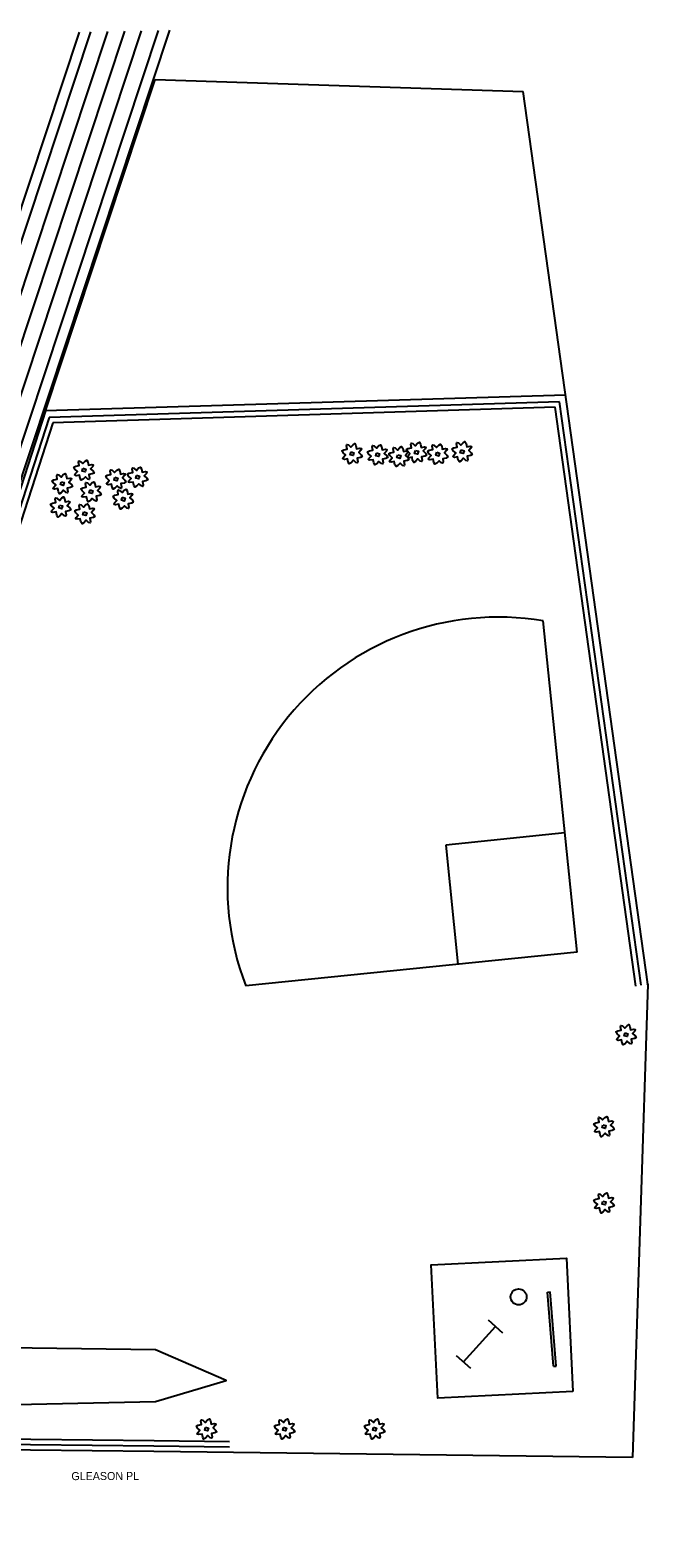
# Model space of a CAD drawing. Extents: x 1810019 to 1811399, y 1074962 to 1076105.
# Drawn here: x 1810935 to 1811399, y 1074973 to 1076105 of the extents above; entities that cross this region are included whole.
import ezdxf

# ---------------------------------------------------------------- set-up
doc = ezdxf.new("R2010")
doc.units = 0
for name, color, linetype in [('Environmental-New trees', 7, 'Continuous'), ('Roadway-Centerline main', 7, 'Continuous'), ('Roadway-Edge of pavement', 7, 'Continuous'), ('Roadway-Edge of shoulder', 7, 'Continuous'), ('Roadway-Land lines', 7, 'Continuous'), ('Roadway-Sidewalks', 7, 'Continuous'), ('Scratch-1', 7, 'Continuous'), ('Text-Route label', 7, 'Continuous')]:
    doc.layers.add(name, color=color, linetype=linetype)

msp = doc.modelspace()

# ---------------------------------------------------------------- linework, layer by layer
at = {"layer": 'Environmental-New trees'}
for points in [[(1811170.3, 1075783.1), (1811170.6, 1075784.2), (1811172.3, 1075786.1), (1811170.4, 1075787.7), (1811169.6, 1075789.1), (1811171, 1075789.9), (1811173.5, 1075790.4), (1811173, 1075792.9), (1811173.3, 1075793.9), (1811174.4, 1075793.6), (1811176.3, 1075791.9), (1811178, 1075793.8), (1811179.3, 1075794.6), (1811180.1, 1075793.2), (1811180.6, 1075790.7), (1811183.1, 1075791.2), (1811184.2, 1075790.9), (1811183.8, 1075789.7), (1811182.2, 1075787.9), (1811184, 1075786.3), (1811184.8, 1075784.9), (1811183.4, 1075784.1), (1811180.9, 1075783.6), (1811181.4, 1075781.1), (1811181.1, 1075780.1), (1811180, 1075780.4), (1811178.2, 1075782.1), (1811176.5, 1075780.2), (1811175.1, 1075779.4), (1811174.3, 1075780.8), (1811173.8, 1075783.3), (1811171.4, 1075782.8)], [(1811189.5, 1075782.4), (1811189.8, 1075783.4), (1811191.5, 1075785.3), (1811189.6, 1075787), (1811188.8, 1075788.4), (1811190.2, 1075789.1), (1811192.7, 1075789.6), (1811192.2, 1075792.1), (1811192.5, 1075793.2), (1811193.6, 1075792.9), (1811195.5, 1075791.2), (1811197.2, 1075793.1), (1811198.5, 1075793.8), (1811199.3, 1075792.4), (1811199.8, 1075790), (1811202.3, 1075790.4), (1811203.3, 1075790.1), (1811203, 1075789), (1811201.3, 1075787.2), (1811203.2, 1075785.5), (1811204, 1075784.1), (1811202.6, 1075783.4), (1811200.1, 1075782.9), (1811200.6, 1075780.4), (1811200.3, 1075779.3), (1811199.2, 1075779.6), (1811197.3, 1075781.3), (1811195.7, 1075779.4), (1811194.3, 1075778.7), (1811193.5, 1075780.1), (1811193, 1075782.5), (1811190.5, 1075782.1)], [(1811205.4, 1075781), (1811205.7, 1075782.1), (1811207.4, 1075783.9), (1811205.5, 1075785.6), (1811204.7, 1075787), (1811206.1, 1075787.8), (1811208.6, 1075788.3), (1811208.1, 1075790.7), (1811208.4, 1075791.8), (1811209.5, 1075791.5), (1811211.4, 1075789.8), (1811213.1, 1075791.7), (1811214.4, 1075792.5), (1811215.2, 1075791.1), (1811215.7, 1075788.6), (1811218.2, 1075789.1), (1811219.3, 1075788.8), (1811218.9, 1075787.6), (1811217.3, 1075785.8), (1811219.1, 1075784.1), (1811219.9, 1075782.7), (1811218.5, 1075782), (1811216, 1075781.5), (1811216.5, 1075779), (1811216.2, 1075777.9), (1811215.1, 1075778.2), (1811213.3, 1075779.9), (1811211.6, 1075778.1), (1811210.2, 1075777.3), (1811209.4, 1075778.7), (1811208.9, 1075781.2), (1811206.5, 1075780.7)], [(1811218.7, 1075784.2), (1811219, 1075785.3), (1811220.7, 1075787.2), (1811218.8, 1075788.9), (1811218.1, 1075790.2), (1811219.4, 1075791), (1811221.9, 1075791.5), (1811221.4, 1075794), (1811221.7, 1075795), (1811222.8, 1075794.7), (1811224.7, 1075793), (1811226.4, 1075794.9), (1811227.8, 1075795.7), (1811228.6, 1075794.3), (1811229, 1075791.8), (1811231.5, 1075792.3), (1811232.6, 1075792), (1811232.2, 1075790.8), (1811230.6, 1075789.1), (1811232.4, 1075787.4), (1811233.2, 1075786), (1811231.9, 1075785.2), (1811229.4, 1075784.7), (1811229.8, 1075782.2), (1811229.5, 1075781.2), (1811228.4, 1075781.5), (1811226.6, 1075783.2), (1811224.9, 1075781.3), (1811223.5, 1075780.5), (1811222.7, 1075781.9), (1811222.3, 1075784.4), (1811219.8, 1075783.9)], [(1811224.9, 1075789.5), (1811227, 1075788.9), (1811226.4, 1075786.7), (1811224.2, 1075787.3)], [(1811234.6, 1075782.8), (1811234.9, 1075783.9), (1811236.6, 1075785.8), (1811234.7, 1075787.5), (1811234, 1075788.9), (1811235.3, 1075789.6), (1811237.8, 1075790.1), (1811237.4, 1075792.6), (1811237.7, 1075793.7), (1811238.7, 1075793.4), (1811240.6, 1075791.7), (1811242.3, 1075793.5), (1811243.7, 1075794.3), (1811244.5, 1075792.9), (1811244.9, 1075790.5), (1811247.4, 1075790.9), (1811248.5, 1075790.6), (1811248.1, 1075789.5), (1811246.5, 1075787.7), (1811248.4, 1075786), (1811249.1, 1075784.6), (1811247.8, 1075783.8), (1811245.3, 1075783.3), (1811245.7, 1075780.9), (1811245.4, 1075779.8), (1811244.4, 1075780.1), (1811242.5, 1075781.8), (1811240.8, 1075779.9), (1811239.4, 1075779.1), (1811238.6, 1075780.5), (1811238.2, 1075783), (1811235.7, 1075782.5)], [(1811253, 1075784.7), (1811253.3, 1075785.7), (1811255, 1075787.6), (1811253.1, 1075789.3), (1811252.3, 1075790.7), (1811253.7, 1075791.4), (1811256.2, 1075791.9), (1811255.7, 1075794.4), (1811256, 1075795.5), (1811257.1, 1075795.2), (1811259, 1075793.5), (1811260.7, 1075795.3), (1811262, 1075796.1), (1811262.8, 1075794.7), (1811263.3, 1075792.3), (1811265.8, 1075792.7), (1811266.8, 1075792.4), (1811266.5, 1075791.3), (1811264.8, 1075789.5), (1811266.7, 1075787.8), (1811267.5, 1075786.4), (1811266.1, 1075785.6), (1811263.6, 1075785.2), (1811264.1, 1075782.7), (1811263.8, 1075781.6), (1811262.7, 1075781.9), (1811260.9, 1075783.6), (1811259.2, 1075781.7), (1811257.8, 1075781), (1811257, 1075782.3), (1811256.5, 1075784.8), (1811254, 1075784.3)], [(1811259.1, 1075789.9), (1811261.3, 1075789.3), (1811260.7, 1075787.2), (1811258.5, 1075787.8)], [(1810969, 1075770.8), (1810969.3, 1075771.9), (1810971, 1075773.7), (1810969.1, 1075775.4), (1810968.3, 1075776.8), (1810969.7, 1075777.6), (1810972.2, 1075778.1), (1810971.7, 1075780.5), (1810972, 1075781.6), (1810973.1, 1075781.3), (1810975, 1075779.6), (1810976.7, 1075781.5), (1810978, 1075782.3), (1810978.8, 1075780.9), (1810979.3, 1075778.4), (1810981.8, 1075778.9), (1810982.8, 1075778.6), (1810982.5, 1075777.4), (1810980.8, 1075775.6), (1810982.7, 1075773.9), (1810983.5, 1075772.5), (1810982.1, 1075771.8), (1810979.6, 1075771.3), (1810980.1, 1075768.8), (1810979.8, 1075767.7), (1810978.7, 1075768), (1810976.9, 1075769.7), (1810975.2, 1075767.9), (1810973.8, 1075767.1), (1810973, 1075768.5), (1810972.5, 1075770.9), (1810970, 1075770.5)], [(1811176.4, 1075788.4), (1811178.6, 1075787.8), (1811178, 1075785.6), (1811175.8, 1075786.2)], [(1811195.6, 1075787.6), (1811197.8, 1075787), (1811197.2, 1075784.9), (1811195, 1075785.5)], [(1811211.5, 1075786.3), (1811213.7, 1075785.7), (1811213.1, 1075783.5), (1811210.9, 1075784.1)], [(1811240.8, 1075788.1), (1811242.9, 1075787.5), (1811242.3, 1075785.3), (1811240.2, 1075786)], [(1810952.6, 1075760.7), (1810952.9, 1075761.7), (1810954.6, 1075763.6), (1810952.7, 1075765.3), (1810952, 1075766.7), (1810953.3, 1075767.4), (1810955.8, 1075767.9), (1810955.4, 1075770.4), (1810955.7, 1075771.5), (1810956.7, 1075771.2), (1810958.6, 1075769.5), (1810960.3, 1075771.3), (1810961.7, 1075772.1), (1810962.5, 1075770.7), (1810962.9, 1075768.3), (1810965.4, 1075768.7), (1810966.5, 1075768.4), (1810966.1, 1075767.3), (1810964.5, 1075765.5), (1810966.4, 1075763.8), (1810967.1, 1075762.4), (1810965.8, 1075761.7), (1810963.3, 1075761.2), (1810963.7, 1075758.7), (1810963.4, 1075757.6), (1810962.4, 1075757.9), (1810960.5, 1075759.6), (1810958.8, 1075757.7), (1810957.4, 1075757), (1810956.6, 1075758.4), (1810956.2, 1075760.8), (1810953.7, 1075760.3)], [(1810975.1, 1075776.1), (1810977.3, 1075775.4), (1810976.7, 1075773.3), (1810974.5, 1075773.9)], [(1810992.8, 1075764.1), (1810993.2, 1075765.1), (1810994.8, 1075767), (1810993, 1075768.7), (1810992.2, 1075770.1), (1810993.6, 1075770.8), (1810996.1, 1075771.3), (1810995.6, 1075773.8), (1810995.9, 1075774.9), (1810997, 1075774.6), (1810998.8, 1075772.9), (1811000.5, 1075774.7), (1811001.9, 1075775.5), (1811002.7, 1075774.1), (1811003.2, 1075771.7), (1811005.6, 1075772.1), (1811006.7, 1075771.8), (1811006.4, 1075770.7), (1811004.7, 1075768.9), (1811006.6, 1075767.2), (1811007.4, 1075765.8), (1811006, 1075765), (1811003.5, 1075764.6), (1811004, 1075762.1), (1811003.7, 1075761), (1811002.6, 1075761.3), (1811000.7, 1075763), (1810999, 1075761.1), (1810997.7, 1075760.4), (1810996.9, 1075761.7), (1810996.4, 1075764.2), (1810993.9, 1075763.7)], [(1810999, 1075769.3), (1811001.2, 1075768.7), (1811000.6, 1075766.6), (1810998.4, 1075767.2)], [(1811009.2, 1075765.6), (1811009.5, 1075766.7), (1811011.2, 1075768.5), (1811009.4, 1075770.2), (1811008.6, 1075771.6), (1811009.9, 1075772.4), (1811012.5, 1075772.9), (1811012, 1075775.3), (1811012.3, 1075776.4), (1811013.4, 1075776.1), (1811015.2, 1075774.4), (1811016.9, 1075776.3), (1811018.3, 1075777), (1811019.1, 1075775.7), (1811019.6, 1075773.2), (1811022, 1075773.7), (1811023.1, 1075773.4), (1811022.7, 1075772.2), (1811021.1, 1075770.4), (1811023, 1075768.7), (1811023.8, 1075767.3), (1811022.4, 1075766.6), (1811019.9, 1075766.1), (1811020.4, 1075763.6), (1811020.1, 1075762.5), (1811019, 1075762.8), (1811017.1, 1075764.5), (1811015.4, 1075762.7), (1811014, 1075761.9), (1811013.3, 1075763.3), (1811012.8, 1075765.7), (1811010.3, 1075765.3)], [(1811015.4, 1075770.9), (1811017.6, 1075770.2), (1811017, 1075768.1), (1811014.8, 1075768.7)], [(1810958.8, 1075765.9), (1810960.9, 1075765.3), (1810960.3, 1075763.2), (1810958.2, 1075763.8)], [(1810974.2, 1075754.6), (1810974.5, 1075755.7), (1810976.2, 1075757.5), (1810974.4, 1075759.2), (1810973.6, 1075760.6), (1810974.9, 1075761.4), (1810977.4, 1075761.8), (1810977, 1075764.3), (1810977.3, 1075765.4), (1810978.4, 1075765.1), (1810980.2, 1075763.4), (1810981.9, 1075765.3), (1810983.3, 1075766), (1810984.1, 1075764.7), (1810984.5, 1075762.2), (1810987, 1075762.7), (1810988.1, 1075762.3), (1810987.7, 1075761.2), (1810986.1, 1075759.4), (1810988, 1075757.7), (1810988.7, 1075756.3), (1810987.4, 1075755.6), (1810984.9, 1075755.1), (1810985.4, 1075752.6), (1810985, 1075751.5), (1810984, 1075751.8), (1810982.1, 1075753.5), (1810980.4, 1075751.7), (1810979, 1075750.9), (1810978.2, 1075752.3), (1810977.8, 1075754.7), (1810975.3, 1075754.3)], [(1810980.4, 1075759.8), (1810982.5, 1075759.2), (1810981.9, 1075757.1), (1810979.8, 1075757.7)], [(1810998.4, 1075749), (1810998.7, 1075750.1), (1811000.4, 1075751.9), (1810998.6, 1075753.6), (1810997.8, 1075755), (1810999.1, 1075755.8), (1811001.6, 1075756.3), (1811001.2, 1075758.7), (1811001.5, 1075759.8), (1811002.6, 1075759.5), (1811004.4, 1075757.8), (1811006.1, 1075759.7), (1811007.5, 1075760.4), (1811008.3, 1075759.1), (1811008.7, 1075756.6), (1811011.2, 1075757.1), (1811012.3, 1075756.8), (1811011.9, 1075755.6), (1811010.3, 1075753.8), (1811012.2, 1075752.1), (1811012.9, 1075750.7), (1811011.6, 1075750), (1811009.1, 1075749.5), (1811009.6, 1075747), (1811009.2, 1075745.9), (1811008.2, 1075746.2), (1811006.3, 1075747.9), (1811004.6, 1075746.1), (1811003.2, 1075745.3), (1811002.4, 1075746.7), (1811002, 1075749.1), (1810999.5, 1075748.7)], [(1810951.4, 1075743.2), (1810951.7, 1075744.3), (1810953.4, 1075746.1), (1810951.5, 1075747.8), (1810950.7, 1075749.2), (1810952.1, 1075750), (1810954.6, 1075750.5), (1810954.1, 1075752.9), (1810954.4, 1075754), (1810955.5, 1075753.7), (1810957.4, 1075752), (1810959.1, 1075753.9), (1810960.5, 1075754.7), (1810961.2, 1075753.3), (1810961.7, 1075750.8), (1810964.2, 1075751.3), (1810965.3, 1075751), (1810964.9, 1075749.8), (1810963.3, 1075748), (1810965.1, 1075746.3), (1810965.9, 1075745), (1810964.5, 1075744.2), (1810962, 1075743.7), (1810962.5, 1075741.2), (1810962.2, 1075740.1), (1810961.1, 1075740.5), (1810959.3, 1075742.1), (1810957.6, 1075740.3), (1810956.2, 1075739.5), (1810955.4, 1075740.9), (1810954.9, 1075743.4), (1810952.5, 1075742.9)], [(1810957.5, 1075748.5), (1810959.7, 1075747.9), (1810959.1, 1075745.7), (1810956.9, 1075746.3)], [(1810969.6, 1075738.1), (1810969.9, 1075739.2), (1810971.6, 1075741), (1810969.7, 1075742.7), (1810968.9, 1075744.1), (1810970.3, 1075744.9), (1810972.8, 1075745.3), (1810972.3, 1075747.8), (1810972.6, 1075748.9), (1810973.7, 1075748.6), (1810975.6, 1075746.9), (1810977.3, 1075748.8), (1810978.6, 1075749.5), (1810979.4, 1075748.2), (1810979.9, 1075745.7), (1810982.4, 1075746.2), (1810983.5, 1075745.9), (1810983.1, 1075744.7), (1810981.5, 1075742.9), (1810983.3, 1075741.2), (1810984.1, 1075739.8), (1810982.7, 1075739.1), (1810980.2, 1075738.6), (1810980.7, 1075736.1), (1810980.4, 1075735), (1810979.3, 1075735.3), (1810977.5, 1075737), (1810975.8, 1075735.2), (1810974.4, 1075734.4), (1810973.6, 1075735.8), (1810973.1, 1075738.2), (1810970.7, 1075737.8)], [(1811004.6, 1075754.3), (1811006.7, 1075753.6), (1811006.1, 1075751.5), (1811004, 1075752.1)], [(1810975.7, 1075743.4), (1810977.9, 1075742.7), (1810977.3, 1075740.6), (1810975.1, 1075741.2)], [(1811376, 1075346.8), (1811376.3, 1075347.9), (1811378, 1075349.8), (1811376.2, 1075351.5), (1811375.4, 1075352.9), (1811376.7, 1075353.6), (1811379.3, 1075354.1), (1811378.8, 1075356.6), (1811379.1, 1075357.7), (1811380.2, 1075357.4), (1811382, 1075355.7), (1811383.7, 1075357.5), (1811385.1, 1075358.3), (1811385.9, 1075356.9), (1811386.4, 1075354.4), (1811388.8, 1075354.9), (1811389.9, 1075354.6), (1811389.5, 1075353.5), (1811387.9, 1075351.7), (1811389.8, 1075350), (1811390.6, 1075348.6), (1811389.2, 1075347.8), (1811386.7, 1075347.3), (1811387.2, 1075344.9), (1811386.9, 1075343.8), (1811385.8, 1075344.1), (1811383.9, 1075345.8), (1811382.2, 1075343.9), (1811380.8, 1075343.1), (1811380.1, 1075344.5), (1811379.6, 1075347), (1811377.1, 1075346.5)], [(1811382.2, 1075352.1), (1811384.4, 1075351.5), (1811383.8, 1075349.3), (1811381.6, 1075349.9)], [(1811359.4, 1075277.9), (1811359.8, 1075279), (1811361.4, 1075280.9), (1811359.6, 1075282.6), (1811358.8, 1075283.9), (1811360.2, 1075284.7), (1811362.7, 1075285.2), (1811362.2, 1075287.7), (1811362.5, 1075288.8), (1811363.6, 1075288.4), (1811365.4, 1075286.8), (1811367.1, 1075288.6), (1811368.5, 1075289.4), (1811369.3, 1075288), (1811369.8, 1075285.5), (1811372.2, 1075286), (1811373.3, 1075285.7), (1811373, 1075284.5), (1811371.3, 1075282.8), (1811373.2, 1075281.1), (1811374, 1075279.7), (1811372.6, 1075278.9), (1811370.1, 1075278.4), (1811370.6, 1075276), (1811370.3, 1075274.9), (1811369.2, 1075275.2), (1811367.3, 1075276.9), (1811365.6, 1075275), (1811364.3, 1075274.2), (1811363.5, 1075275.6), (1811363, 1075278.1), (1811360.5, 1075277.6)], [(1811365.6, 1075283.2), (1811367.8, 1075282.6), (1811367.2, 1075280.4), (1811365, 1075281)], [(1811359.4, 1075220.5), (1811359.8, 1075221.6), (1811361.4, 1075223.4), (1811359.6, 1075225.1), (1811358.8, 1075226.5), (1811360.2, 1075227.3), (1811362.7, 1075227.8), (1811362.2, 1075230.2), (1811362.5, 1075231.3), (1811363.6, 1075231), (1811365.4, 1075229.3), (1811367.1, 1075231.2), (1811368.5, 1075232), (1811369.3, 1075230.6), (1811369.8, 1075228.1), (1811372.2, 1075228.6), (1811373.3, 1075228.3), (1811373, 1075227.1), (1811371.3, 1075225.3), (1811373.2, 1075223.6), (1811374, 1075222.2), (1811372.6, 1075221.5), (1811370.1, 1075221), (1811370.6, 1075218.5), (1811370.3, 1075217.4), (1811369.2, 1075217.7), (1811367.3, 1075219.4), (1811365.6, 1075217.6), (1811364.3, 1075216.8), (1811363.5, 1075218.2), (1811363, 1075220.7), (1811360.5, 1075220.2)], [(1811365.6, 1075225.8), (1811367.8, 1075225.2), (1811367.2, 1075223), (1811365, 1075223.6)], [(1811060.9, 1075050.8), (1811061.2, 1075051.8), (1811062.9, 1075053.7), (1811061.1, 1075055.4), (1811060.3, 1075056.8), (1811061.6, 1075057.5), (1811064.2, 1075058), (1811063.7, 1075060.5), (1811064, 1075061.6), (1811065.1, 1075061.3), (1811066.9, 1075059.6), (1811068.6, 1075061.5), (1811070, 1075062.2), (1811070.8, 1075060.8), (1811071.3, 1075058.4), (1811073.7, 1075058.8), (1811074.8, 1075058.5), (1811074.4, 1075057.4), (1811072.8, 1075055.6), (1811074.7, 1075053.9), (1811075.5, 1075052.5), (1811074.1, 1075051.8), (1811071.6, 1075051.3), (1811072.1, 1075048.8), (1811071.8, 1075047.7), (1811070.7, 1075048), (1811068.8, 1075049.7), (1811067.1, 1075047.9), (1811065.7, 1075047.1), (1811065, 1075048.5), (1811064.5, 1075050.9), (1811062, 1075050.5)], [(1811067.1, 1075056), (1811069.3, 1075055.4), (1811068.7, 1075053.3), (1811066.5, 1075053.9)], [(1811119.6, 1075050.8), (1811119.9, 1075051.8), (1811121.6, 1075053.7), (1811119.8, 1075055.4), (1811119, 1075056.8), (1811120.3, 1075057.5), (1811122.8, 1075058), (1811122.4, 1075060.5), (1811122.7, 1075061.6), (1811123.7, 1075061.3), (1811125.6, 1075059.6), (1811127.3, 1075061.5), (1811128.7, 1075062.2), (1811129.5, 1075060.8), (1811129.9, 1075058.4), (1811132.4, 1075058.8), (1811133.5, 1075058.5), (1811133.1, 1075057.4), (1811131.5, 1075055.6), (1811133.4, 1075053.9), (1811134.1, 1075052.5), (1811132.8, 1075051.8), (1811130.3, 1075051.3), (1811130.8, 1075048.8), (1811130.4, 1075047.7), (1811129.4, 1075048), (1811127.5, 1075049.7), (1811125.8, 1075047.9), (1811124.4, 1075047.1), (1811123.6, 1075048.5), (1811123.2, 1075050.9), (1811120.7, 1075050.5)], [(1811125.8, 1075056), (1811127.9, 1075055.4), (1811127.3, 1075053.3), (1811125.2, 1075053.9)], [(1811187.2, 1075050.8), (1811187.5, 1075051.8), (1811189.2, 1075053.7), (1811187.4, 1075055.4), (1811186.6, 1075056.8), (1811187.9, 1075057.5), (1811190.4, 1075058), (1811190, 1075060.5), (1811190.3, 1075061.6), (1811191.4, 1075061.3), (1811193.2, 1075059.6), (1811194.9, 1075061.5), (1811196.3, 1075062.2), (1811197.1, 1075060.8), (1811197.6, 1075058.4), (1811200, 1075058.8), (1811201.1, 1075058.5), (1811200.7, 1075057.4), (1811199.1, 1075055.6), (1811201, 1075053.9), (1811201.8, 1075052.5), (1811200.4, 1075051.8), (1811197.9, 1075051.3), (1811198.4, 1075048.8), (1811198.1, 1075047.7), (1811197, 1075048), (1811195.1, 1075049.7), (1811193.4, 1075047.9), (1811192, 1075047.1), (1811191.3, 1075048.5), (1811190.8, 1075050.9), (1811188.3, 1075050.5)], [(1811193.4, 1075056), (1811195.6, 1075055.4), (1811194.9, 1075053.3), (1811192.8, 1075053.9)]]:
    msp.add_lwpolyline(points, close=True, dxfattribs=at)
msp.add_lwpolyline([(1810835.9, 1075357.3), (1810791.1, 1075207.2), (1810750, 1075091.1), (1810808.1, 1075070.5), (1811029.5, 1075075.4), (1811082.7, 1075091.1), (1811029.5, 1075114.1), (1810862.5, 1075116.5), (1810845.6, 1075189.1), (1810869.8, 1075325.8), (1810838.3, 1075356.1)], dxfattribs=at)
at = {"layer": 'Roadway-Centerline main'}
msp.add_line((1811006.2, 1076104.4), (1810632.2, 1074976.4), dxfattribs=at)
at = {"layer": 'Roadway-Edge of pavement'}
for p, q in [((1810980.7, 1076103.8), (1810606, 1074973.8)), ((1810993.4, 1076104.1), (1810619.1, 1074975.1)), ((1811018.9, 1076104.6), (1810645.2, 1074977.7)), ((1811031.6, 1076104.9), (1810658.3, 1074978.9))]:
    msp.add_line(p, q, dxfattribs=at)
at = {"layer": 'Roadway-Edge of shoulder'}
for p, q in [((1810972.2, 1076103.6), (1810597.3, 1074973)), ((1811040.1, 1076105.1), (1810667, 1074979.8))]:
    msp.add_line(p, q, dxfattribs=at)
at = {"layer": 'Roadway-Land lines'}
for p, q in [((1810946.9, 1075819.1), (1811029.3, 1076068.1)), ((1811029.3, 1076068.1), (1811305.6, 1076059.1)), ((1811399.3, 1075388.6), (1811305.6, 1076059.1)), ((1811337.5, 1075831.1), (1810946.9, 1075819.1)), ((1810946.9, 1075819.1), (1810694.6, 1075041.8)), ((1811399.3, 1075388.6), (1811387.7, 1075033.4)), ((1811398.5, 1075388.5), (1811399.3, 1075388.6)), ((1810935.8, 1075038.9), (1810842.5, 1075040.1)), ((1811028.4, 1075037.8), (1810935.8, 1075038.9)), ((1811387.7, 1075033.4), (1811028.4, 1075037.8))]:
    msp.add_line(p, q, dxfattribs=at)
at = {"layer": 'Roadway-Sidewalks'}
for p, q in [((1811333.1, 1075826), (1810949.6, 1075814.1)), ((1811394.4, 1075387.9), (1811333.1, 1075826)), ((1810949.6, 1075814.1), (1810700.1, 1075045.7)), ((1811329.7, 1075821.9), (1810952.5, 1075810.2)), ((1811390.4, 1075387.3), (1811329.7, 1075821.9)), ((1810952.5, 1075810.2), (1810705.6, 1075049.7)), ((1810935.8, 1075042.9), (1810842.5, 1075044.1)), ((1810935.9, 1075046.9), (1810842.6, 1075048.1)), ((1811028.4, 1075041.8), (1810935.8, 1075042.9)), ((1811028.5, 1075045.8), (1810935.9, 1075046.9)), ((1811085.2, 1075045.1), (1811028.5, 1075045.8)), ((1811085.1, 1075041.1), (1811028.4, 1075041.8))]:
    msp.add_line(p, q, dxfattribs=at)
at = {"layer": 'Scratch-1'}
for p, q in [((1811346.2, 1075412.8), (1811320.8, 1075661.5)), ((1811337, 1075502.3), (1811247.5, 1075493.2)), ((1811247.5, 1075493.2), (1811256.6, 1075403.7)), ((1811346.2, 1075412.8), (1811097.4, 1075387.4)), ((1811323.9, 1075157.5), (1811325.9, 1075157.7)), ((1811328.4, 1075101.8), (1811323.9, 1075157.5)), ((1811330.4, 1075101.9), (1811325.9, 1075157.7)), ((1811279.5, 1075136.6), (1811290.2, 1075126.8)), ((1811260.8, 1075105.2), (1811284.8, 1075131.7)), ((1811255.5, 1075110), (1811266.2, 1075100.3)), ((1811328.4, 1075101.8), (1811330.4, 1075101.9))]:
    msp.add_line(p, q, dxfattribs=at)
msp.add_lwpolyline([(1811343, 1075082.9), (1811241.6, 1075077.9), (1811236.7, 1075178), (1811338.2, 1075183)], close=True, dxfattribs=at)
msp.add_circle((1811302.3, 1075153.9), 6, dxfattribs=at)
msp.add_arc((1811286.9, 1075461), 203.3, 80.4255, 201.2316, dxfattribs=at)

# ---------------------------------------------------------------- texts
at = {"layer": 'Text-Route label'}
msp.add_text('GLEASON PL', height=6, rotation=0.1789, dxfattribs=at).set_placement((1810966.4, 1075016.3))

doc.saveas('drawing.dxf')
